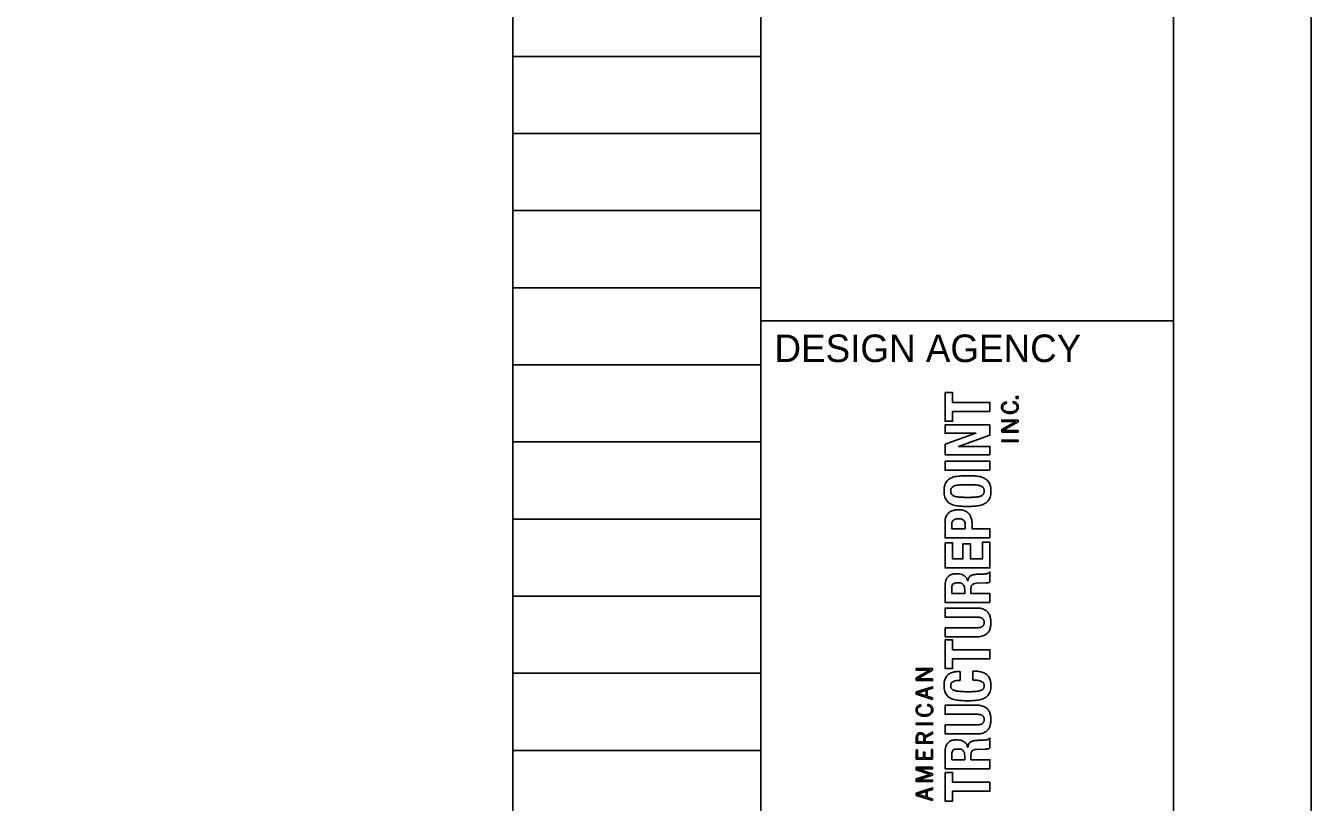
# Model space of a CAD drawing. Extents: x 0 to 84.3, y -13.4 to 22.
# Drawn here: x 29.33 to 34, y 2.751 to 5.571 of the extents above; entities that cross this region are included whole.
import ezdxf

# ---------------------------------------------------------------- set-up
doc = ezdxf.new("R2010")
doc.units = 0
for name, color, linetype in [('SH_Border', 7, 'Continuous'), ('SH_Cut_Line', 7, 'Continuous'), ('SH_Data', 7, 'Continuous')]:
    doc.layers.add(name, color=color, linetype=linetype)

msp = doc.modelspace()

# ---------------------------------------------------------------- linework, layer by layer
at = {"layer": 'SH_Border'}
for p, q in [((32, 0.5), (32, 21.5)), ((32, 4.5), (33.5, 4.5))]:
    msp.add_line(p, q, dxfattribs=at)
msp.add_lwpolyline([(1.5, 21.5), (33.5, 21.5), (33.5, 0.5), (1.5, 0.5)], close=True, dxfattribs=at)
at = {"layer": 'SH_Cut_Line'}
msp.add_lwpolyline([(0, 0), (34, 0), (34, 22), (0, 22)], close=True, dxfattribs=at)
at = {"layer": 'SH_Data'}
for p, q in [((31.1, 0.98), (31.1, 21.14)), ((32, 0.98), (32, 21.14)), ((31.1, 5.46), (32, 5.46)), ((31.1, 5.18), (32, 5.18)), ((31.1, 4.9), (32, 4.9)), ((31.1, 4.62), (32, 4.62)), ((31.1, 4.34), (32, 4.34)), ((31.1, 4.06), (32, 4.06)), ((31.1, 3.78), (32, 3.78)), ((31.1, 3.5), (32, 3.5)), ((32.75, 3.5), (32.75, 3.5)), ((32.75, 3.5), (32.75, 3.5)), ((31.1, 3.22), (32, 3.22)), ((31.1, 2.94), (32, 2.94))]:
    msp.add_line(p, q, dxfattribs=at)
for points in [[(32.6696, 4.2393), (32.6967, 4.2393), (32.6967, 4.2036), (32.8329, 4.2036), (32.8329, 4.1708), (32.6967, 4.1708), (32.6967, 4.1351), (32.6696, 4.1351), (32.6696, 4.2393)], [(32.9349, 4.218), (32.9275, 4.218), (32.9275, 4.225), (32.9349, 4.225), (32.9349, 4.218)], [(32.6696, 4.0513), (32.7815, 4.0912), (32.7815, 4.0916), (32.6696, 4.0916), (32.6696, 4.1218), (32.8329, 4.1218), (32.8329, 4.0842), (32.7185, 4.0439), (32.7185, 4.0435), (32.8329, 4.0435), (32.8329, 4.0134), (32.6696, 4.0134), (32.6696, 4.0513)], [(32.8754, 4.096), (32.8754, 4.1052), (32.925, 4.1335), (32.925, 4.1337), (32.8754, 4.1337), (32.8754, 4.1391), (32.9349, 4.1391), (32.9349, 4.1335), (32.8798, 4.1016), (32.8798, 4.1014), (32.9349, 4.1014), (32.9349, 4.096), (32.8754, 4.096)], [(32.8754, 4.0613), (32.8754, 4.0667), (32.9349, 4.0667), (32.9349, 4.0613), (32.8754, 4.0613)], [(32.8329, 3.957), (32.6696, 3.957), (32.6696, 3.9898), (32.8329, 3.9898), (32.8329, 3.957)], [(32.8329, 3.7115), (32.6696, 3.7115), (32.6696, 3.7691)], [(32.694, 3.7444), (32.7432, 3.7444), (32.7432, 3.759)], [(32.694, 3.7581), (32.694, 3.7444)], [(32.7677, 3.7619), (32.7677, 3.7444), (32.8329, 3.7444), (32.8329, 3.7115)], [(32.6696, 3.6937), (32.6967, 3.6937), (32.6967, 3.6353), (32.7348, 3.6353), (32.7348, 3.6903), (32.7619, 3.6903), (32.7619, 3.6353), (32.8058, 3.6353), (32.8058, 3.696), (32.8329, 3.696), (32.8329, 3.6025), (32.6696, 3.6025), (32.6696, 3.6937)], [(32.7519, 3.5538), (32.7524, 3.5538)], [(32.8316, 3.5875), (32.8329, 3.5875), (32.8329, 3.5518)], [(32.8329, 3.4763), (32.6696, 3.4763), (32.6696, 3.5373)], [(32.694, 3.5249), (32.694, 3.5092)], [(32.694, 3.5092), (32.7409, 3.5092), (32.7409, 3.5231)], [(32.7638, 3.527), (32.7638, 3.5092), (32.8329, 3.5092), (32.8329, 3.4763)], [(32.8158, 3.5477), (32.7844, 3.5468)], [(32.6696, 3.3411), (32.6967, 3.3411), (32.6967, 3.3054), (32.8329, 3.3054), (32.8329, 3.2726), (32.6967, 3.2726), (32.6967, 3.2369), (32.6696, 3.2369), (32.6696, 3.3411)], [(32.565, 3.1938), (32.565, 3.2029), (32.6146, 3.2313), (32.6146, 3.2315), (32.565, 3.2315), (32.565, 3.2369), (32.6245, 3.2369), (32.6245, 3.2313), (32.5694, 3.1994), (32.5694, 3.1992), (32.6245, 3.1992), (32.6245, 3.1938), (32.565, 3.1938)], [(32.6245, 3.1249), (32.565, 3.1439), (32.565, 3.1523), (32.6245, 3.1711), (32.6245, 3.1653), (32.605, 3.1593), (32.605, 3.1368), (32.6245, 3.1307), (32.6245, 3.1249)], [(32.6006, 3.1382), (32.6006, 3.158), (32.5694, 3.1481), (32.5694, 3.148), (32.6006, 3.1382)], [(32.565, 3.0336), (32.565, 3.039), (32.6245, 3.039), (32.6245, 3.0336), (32.565, 3.0336)], [(32.5963, 2.9917), (32.6245, 3.0063), (32.6245, 3.0004), (32.5973, 2.9865), (32.5973, 2.9711), (32.6245, 2.9711), (32.6245, 2.9656), (32.565, 2.9656), (32.565, 2.9858)], [(32.6245, 2.9074), (32.565, 2.9074), (32.565, 2.9414), (32.5694, 2.9414), (32.5694, 2.9129), (32.5913, 2.9129), (32.5913, 2.9334), (32.5958, 2.9334), (32.5958, 2.9129), (32.62, 2.9129), (32.62, 2.943), (32.6245, 2.943), (32.6245, 2.9074)], [(32.5694, 2.9711), (32.5928, 2.9711), (32.5928, 2.9858)], [(32.5694, 2.9858), (32.5694, 2.9711)], [(32.7519, 2.9506), (32.7524, 2.9506)], [(32.8158, 2.9445), (32.7844, 2.9435)], [(32.8316, 2.9843), (32.8329, 2.9843), (32.8329, 2.9486)], [(32.8329, 2.8731), (32.6696, 2.8731), (32.6696, 2.9341)], [(32.694, 2.9217), (32.694, 2.9059)], [(32.694, 2.9059), (32.7409, 2.9059), (32.7409, 2.9198)], [(32.7638, 2.9238), (32.7638, 2.9059), (32.8329, 2.9059), (32.8329, 2.8731)], [(32.6245, 2.8264), (32.565, 2.8264), (32.565, 2.836), (32.6154, 2.8524), (32.6154, 2.8526), (32.565, 2.8691), (32.565, 2.8787), (32.6245, 2.8787), (32.6245, 2.8732), (32.5694, 2.8732), (32.5694, 2.8731), (32.6245, 2.8551), (32.6245, 2.8499), (32.5694, 2.832), (32.5694, 2.8318), (32.6245, 2.8318), (32.6245, 2.8264)], [(32.6696, 2.86), (32.6967, 2.86), (32.6967, 2.8242), (32.8329, 2.8242), (32.8329, 2.7914), (32.6967, 2.7914), (32.6967, 2.7557), (32.6696, 2.7557), (32.6696, 2.86)], [(32.6245, 2.7575), (32.565, 2.7766), (32.565, 2.7849), (32.6245, 2.8037), (32.6245, 2.7979), (32.605, 2.7919), (32.605, 2.7694), (32.6245, 2.7633), (32.6245, 2.7575)], [(32.6006, 2.7708), (32.6006, 2.7906), (32.5694, 2.7808), (32.5694, 2.7806), (32.6006, 2.7708)]]:
    msp.add_lwpolyline(points, dxfattribs=at)
for points in [[(32.8929, 4.2005), (32.8885, 4.1993), (32.8851, 4.1974), (32.8827, 4.195), (32.8803, 4.1926), (32.8791, 4.1896), (32.8791, 4.186), (32.8791, 4.183), (32.8798, 4.1805), (32.8811, 4.1784), (32.8825, 4.1763), (32.8843, 4.1745), (32.8867, 4.1731), (32.889, 4.1717), (32.8918, 4.1707), (32.895, 4.17), (32.8982, 4.1694), (32.9016, 4.169), (32.9052, 4.169), (32.9088, 4.169), (32.9122, 4.1694), (32.9154, 4.17), (32.9186, 4.1707), (32.9214, 4.1717), (32.9237, 4.1732), (32.9261, 4.1746), (32.9279, 4.1764), (32.9293, 4.1786), (32.9306, 4.1809), (32.9313, 4.1835), (32.9313, 4.1866), (32.9313, 4.189), (32.9309, 4.191), (32.9301, 4.1927), (32.9293, 4.1943), (32.9283, 4.1957), (32.9269, 4.1969), (32.9256, 4.1981), (32.9241, 4.199), (32.9223, 4.1997), (32.9206, 4.2005), (32.9187, 4.2011), (32.9168, 4.2016), (32.9168, 4.2016), (32.9177, 4.2067), (32.9177, 4.2067), (32.9203, 4.2062), (32.9228, 4.2054), (32.925, 4.2044), (32.9272, 4.2033), (32.9291, 4.202), (32.9307, 4.2004), (32.9323, 4.1988), (32.9336, 4.1969), (32.9345, 4.1946), (32.9354, 4.1924), (32.9358, 4.1896), (32.9358, 4.1865), (32.9358, 4.1829), (32.9351, 4.1797), (32.9336, 4.1768), (32.9322, 4.174), (32.9301, 4.1716), (32.9274, 4.1697), (32.9247, 4.1677), (32.9215, 4.1662), (32.9177, 4.1652), (32.914, 4.1641), (32.9098, 4.1636), (32.9052, 4.1636), (32.9006, 4.1636), (32.8964, 4.1641), (32.8927, 4.1652), (32.889, 4.1662), (32.8857, 4.1677), (32.883, 4.1697), (32.8803, 4.1716), (32.8783, 4.174), (32.8768, 4.1768), (32.8754, 4.1797), (32.8746, 4.1829), (32.8746, 4.1865), (32.8746, 4.1891), (32.8751, 4.1915), (32.8759, 4.1936), (32.8768, 4.1957), (32.878, 4.1975), (32.8796, 4.1991), (32.8811, 4.2006), (32.8829, 4.202), (32.885, 4.203), (32.8871, 4.204), (32.8894, 4.2049), (32.8918, 4.2056), (32.8918, 4.2056), (32.8929, 4.2005), (32.8929, 4.2005)], [(32.7511, 3.8258), (32.7387, 3.8258), (32.7273, 3.8264), (32.7168, 3.8275), (32.7064, 3.8287), (32.6974, 3.8312), (32.6899, 3.8351), (32.6825, 3.839), (32.6766, 3.8446), (32.6724, 3.8519), (32.6682, 3.8593), (32.6661, 3.8691), (32.6661, 3.8815), (32.6661, 3.8939), (32.6682, 3.9038), (32.6724, 3.9111), (32.6766, 3.9184), (32.6825, 3.9241), (32.6899, 3.928), (32.6974, 3.9319), (32.7064, 3.9344), (32.7168, 3.9355), (32.7273, 3.9367), (32.7387, 3.9373), (32.7511, 3.9373), (32.7578, 3.9373), (32.7643, 3.9371), (32.7705, 3.9367)], [(32.7705, 3.9367), (32.7756, 3.9365), (32.7806, 3.9361), (32.7853, 3.9355), (32.7957, 3.9344), (32.8047, 3.9319), (32.8122, 3.928), (32.8197, 3.9241), (32.8255, 3.9184), (32.8297, 3.9111), (32.8339, 3.9038), (32.836, 3.8939), (32.836, 3.8815), (32.836, 3.8691), (32.8339, 3.8593), (32.8297, 3.8519), (32.8255, 3.8446), (32.8197, 3.839), (32.8122, 3.8351), (32.8047, 3.8312), (32.7957, 3.8287), (32.7853, 3.8275), (32.7748, 3.8264), (32.7634, 3.8258), (32.7511, 3.8258)], [(32.7511, 3.8586), (32.762, 3.8586), (32.7713, 3.8589), (32.779, 3.8594), (32.7867, 3.86), (32.7929, 3.8611), (32.7978, 3.8627), (32.8025, 3.8643), (32.806, 3.8666), (32.8082, 3.8696), (32.8105, 3.8726), (32.8116, 3.8766), (32.8116, 3.8815), (32.8116, 3.8865), (32.8105, 3.8904), (32.8082, 3.8934), (32.806, 3.8964), (32.8025, 3.8988), (32.7978, 3.9004), (32.7929, 3.902), (32.7867, 3.9031), (32.779, 3.9036), (32.7713, 3.9042), (32.762, 3.9044), (32.7511, 3.9044), (32.7401, 3.9044), (32.7308, 3.9042), (32.7232, 3.9036), (32.7156, 3.9031), (32.7094, 3.902), (32.7045, 3.9004), (32.6996, 3.8988), (32.6961, 3.8964), (32.6939, 3.8934), (32.6917, 3.8904), (32.6906, 3.8865), (32.6906, 3.8815), (32.6906, 3.8766), (32.6917, 3.8726), (32.6939, 3.8696), (32.6961, 3.8666), (32.6996, 3.8643), (32.7045, 3.8627), (32.7094, 3.8611), (32.7156, 3.86), (32.7232, 3.8594), (32.7308, 3.8589), (32.7401, 3.8586), (32.7511, 3.8586)], [(32.6696, 3.7691), (32.6696, 3.7774), (32.671, 3.7845), (32.6738, 3.7902), (32.6766, 3.7959), (32.6803, 3.8005), (32.6849, 3.804), (32.6895, 3.8075), (32.6947, 3.81), (32.7005, 3.8115), (32.7064, 3.8131), (32.7124, 3.8138), (32.7185, 3.8138), (32.727, 3.8138), (32.7344, 3.8126), (32.7406, 3.8101), (32.7467, 3.8075), (32.7518, 3.804), (32.7558, 3.7995), (32.7597, 3.795), (32.7627, 3.7896), (32.7647, 3.7832), (32.7667, 3.7768), (32.7677, 3.7697), (32.7677, 3.7619)], [(32.7432, 3.759), (32.7432, 3.7656), (32.7413, 3.7709), (32.7373, 3.7749), (32.7334, 3.779), (32.7273, 3.781), (32.719, 3.781), (32.7109, 3.781), (32.7048, 3.7792), (32.7005, 3.7757), (32.6962, 3.7722), (32.694, 3.7663), (32.694, 3.7581)], [(32.6696, 3.5373), (32.6696, 3.5509), (32.6731, 3.5616), (32.6801, 3.5693), (32.6871, 3.5771), (32.6976, 3.5809), (32.7117, 3.5809), (32.7227, 3.5809), (32.7316, 3.5787), (32.7386, 3.5743), (32.7455, 3.5699), (32.75, 3.5631), (32.7519, 3.5538)], [(32.7524, 3.5538), (32.7532, 3.5594), (32.7546, 3.5639), (32.7566, 3.5673), (32.7587, 3.5707), (32.7617, 3.5733), (32.7655, 3.5752), (32.7694, 3.5771), (32.7744, 3.5784), (32.7803, 3.579), (32.7863, 3.5796), (32.7936, 3.58), (32.8023, 3.5802), (32.811, 3.5803), (32.8176, 3.5808), (32.8222, 3.5816), (32.8268, 3.5825), (32.8299, 3.5844), (32.8316, 3.5875)], [(32.8329, 3.5518), (32.8307, 3.5501), (32.828, 3.5491), (32.825, 3.5486), (32.8221, 3.5482), (32.819, 3.5479), (32.8158, 3.5477)], [(32.7409, 3.5231), (32.7409, 3.5311), (32.7391, 3.5373), (32.7354, 3.5416), (32.7316, 3.5459), (32.7254, 3.5481), (32.7166, 3.5481), (32.7015, 3.5481), (32.694, 3.5404), (32.694, 3.5249)], [(32.7844, 3.5468), (32.778, 3.5465), (32.773, 3.5448), (32.7693, 3.5418), (32.7657, 3.5388), (32.7638, 3.5338), (32.7638, 3.527)], [(32.6696, 3.3852), (32.6696, 3.3852), (32.7832, 3.3852), (32.7832, 3.3852), (32.7874, 3.3852), (32.7911, 3.3854), (32.7946, 3.386), (32.798, 3.3865), (32.8009, 3.3875), (32.8035, 3.389), (32.806, 3.3904), (32.8079, 3.3924), (32.8094, 3.3949), (32.8108, 3.3975), (32.8116, 3.4006), (32.8116, 3.4045), (32.8116, 3.4083), (32.8108, 3.4115), (32.8094, 3.414), (32.8079, 3.4165), (32.806, 3.4185), (32.8035, 3.4199), (32.8009, 3.4214), (32.798, 3.4224), (32.7946, 3.4229), (32.7911, 3.4235), (32.7874, 3.4237), (32.7832, 3.4237), (32.7832, 3.4237), (32.6696, 3.4237), (32.6696, 3.4237), (32.6696, 3.4237), (32.6696, 3.4566), (32.6696, 3.4566), (32.6696, 3.4566), (32.7834, 3.4566), (32.7834, 3.4566), (32.7938, 3.4566), (32.8023, 3.4551), (32.8091, 3.4522), (32.8159, 3.4493), (32.8213, 3.4454), (32.8252, 3.4406), (32.8292, 3.4357), (32.832, 3.4301), (32.8336, 3.4239), (32.8352, 3.4176), (32.836, 3.4112), (32.836, 3.4045), (32.836, 3.3978), (32.8353, 3.3913), (32.8339, 3.385), (32.8326, 3.3788), (32.8299, 3.3732), (32.826, 3.3683), (32.8222, 3.3635), (32.8168, 3.3596), (32.81, 3.3567), (32.8033, 3.3538), (32.7944, 3.3524), (32.7834, 3.3524), (32.7834, 3.3524), (32.6696, 3.3524), (32.6696, 3.3524), (32.6696, 3.3524), (32.6696, 3.3852), (32.6696, 3.3852)], [(32.7247, 3.1935), (32.7128, 3.1935), (32.7041, 3.1921), (32.6987, 3.1892), (32.6933, 3.1864), (32.6906, 3.1812), (32.6906, 3.1737), (32.6906, 3.1696), (32.6917, 3.1662), (32.6939, 3.1635), (32.6961, 3.1608), (32.6997, 3.1587), (32.7046, 3.1572), (32.7095, 3.1556), (32.716, 3.1546), (32.724, 3.154), (32.732, 3.1533), (32.7418, 3.153), (32.7533, 3.153), (32.7657, 3.153), (32.7756, 3.1535), (32.7832, 3.1543), (32.7909, 3.1551), (32.7968, 3.1565), (32.8009, 3.1582), (32.8051, 3.16), (32.8079, 3.1622), (32.8094, 3.1649), (32.8108, 3.1676), (32.8116, 3.1707), (32.8116, 3.1743), (32.8116, 3.1772), (32.8111, 3.1799), (32.8101, 3.1824), (32.8091, 3.185), (32.8071, 3.1872), (32.8041, 3.189), (32.8011, 3.1909), (32.7969, 3.1923), (32.7915, 3.1934), (32.7861, 3.1945), (32.779, 3.195), (32.7701, 3.195), (32.7701, 3.195), (32.7701, 3.2279), (32.7701, 3.2279), (32.779, 3.2279), (32.7874, 3.2272), (32.7953, 3.2258), (32.8032, 3.2244), (32.8102, 3.2219), (32.8163, 3.2181), (32.8224, 3.2144), (32.8272, 3.2091), (32.8307, 3.2023), (32.8342, 3.1955), (32.836, 3.1867), (32.836, 3.1759), (32.836, 3.1635), (32.8339, 3.1536), (32.8297, 3.1463), (32.8255, 3.139), (32.8197, 3.1334), (32.8122, 3.1295), (32.8047, 3.1256), (32.7957, 3.1231), (32.7853, 3.1219), (32.7748, 3.1208), (32.7634, 3.1202), (32.7511, 3.1202), (32.7387, 3.1202), (32.7273, 3.1208), (32.7168, 3.1219), (32.7064, 3.1231), (32.6974, 3.1256), (32.6899, 3.1295), (32.6825, 3.1334), (32.6766, 3.139), (32.6724, 3.1463), (32.6682, 3.1536), (32.6661, 3.1634), (32.6661, 3.1758), (32.6661, 3.1875), (32.6681, 3.1968), (32.6719, 3.2036), (32.6757, 3.2104), (32.6806, 3.2154), (32.6865, 3.2188), (32.6924, 3.2221), (32.6988, 3.2242), (32.7056, 3.2251), (32.7124, 3.2259), (32.7187, 3.2263), (32.7247, 3.2263), (32.7247, 3.2263), (32.7247, 3.1935), (32.7247, 3.1935)], [(32.5824, 3.1009), (32.5781, 3.0997), (32.5747, 3.0978), (32.5723, 3.0954), (32.5699, 3.0931), (32.5687, 3.09), (32.5687, 3.0864), (32.5687, 3.0835), (32.5694, 3.0809), (32.5707, 3.0788), (32.572, 3.0767), (32.5739, 3.0749), (32.5763, 3.0735), (32.5786, 3.0721), (32.5814, 3.0711), (32.5846, 3.0704), (32.5878, 3.0698), (32.5912, 3.0694), (32.5948, 3.0694), (32.5984, 3.0694), (32.6018, 3.0698), (32.605, 3.0704), (32.6082, 3.0711), (32.6109, 3.0721), (32.6133, 3.0736), (32.6157, 3.075), (32.6175, 3.0768), (32.6189, 3.079), (32.6202, 3.0813), (32.6209, 3.0839), (32.6209, 3.087), (32.6209, 3.0894), (32.6205, 3.0914), (32.6197, 3.0931), (32.6189, 3.0947), (32.6178, 3.0961), (32.6165, 3.0973), (32.6152, 3.0985), (32.6137, 3.0994), (32.6119, 3.1001), (32.6101, 3.1009), (32.6083, 3.1015), (32.6064, 3.102), (32.6064, 3.102), (32.6073, 3.1071), (32.6073, 3.1071), (32.6099, 3.1066), (32.6124, 3.1058), (32.6146, 3.1048), (32.6168, 3.1037), (32.6187, 3.1024), (32.6203, 3.1008), (32.6219, 3.0992), (32.6232, 3.0973), (32.624, 3.095), (32.6249, 3.0927), (32.6254, 3.09), (32.6254, 3.0869), (32.6254, 3.0833), (32.6246, 3.0801), (32.6232, 3.0772), (32.6217, 3.0744), (32.6197, 3.072), (32.617, 3.0701), (32.6143, 3.0681), (32.611, 3.0666), (32.6073, 3.0656), (32.6036, 3.0645), (32.5994, 3.064), (32.5948, 3.064), (32.5902, 3.064), (32.586, 3.0645), (32.5823, 3.0656), (32.5785, 3.0666), (32.5753, 3.0681), (32.5726, 3.0701), (32.5699, 3.072), (32.5678, 3.0744), (32.5664, 3.0772), (32.5649, 3.0801), (32.5642, 3.0833), (32.5642, 3.0869), (32.5642, 3.0895), (32.5646, 3.0919), (32.5655, 3.094), (32.5664, 3.0961), (32.5676, 3.0979), (32.5691, 3.0995), (32.5707, 3.1011), (32.5725, 3.1024), (32.5746, 3.1034), (32.5767, 3.1044), (32.579, 3.1053), (32.5814, 3.106), (32.5814, 3.106), (32.5824, 3.1009), (32.5824, 3.1009)], [(32.6696, 3.0325), (32.6696, 3.0325), (32.7832, 3.0325), (32.7832, 3.0325), (32.7874, 3.0325), (32.7911, 3.0328), (32.7946, 3.0333), (32.798, 3.0338), (32.8009, 3.0348), (32.8035, 3.0363), (32.806, 3.0377), (32.8079, 3.0397), (32.8094, 3.0422), (32.8108, 3.0448), (32.8116, 3.0479), (32.8116, 3.0518), (32.8116, 3.0556), (32.8108, 3.0588), (32.8094, 3.0613), (32.8079, 3.0638), (32.806, 3.0658), (32.8035, 3.0673), (32.8009, 3.0687), (32.798, 3.0697), (32.7946, 3.0702), (32.7911, 3.0708), (32.7874, 3.071), (32.7832, 3.071), (32.7832, 3.071), (32.6696, 3.071), (32.6696, 3.071), (32.6696, 3.071), (32.6696, 3.1039), (32.6696, 3.1039), (32.6696, 3.1039), (32.7834, 3.1039), (32.7834, 3.1039), (32.7938, 3.1039), (32.8023, 3.1024), (32.8091, 3.0995), (32.8159, 3.0966), (32.8213, 3.0928), (32.8252, 3.0879), (32.8292, 3.083), (32.832, 3.0774), (32.8336, 3.0712), (32.8352, 3.0649), (32.836, 3.0585), (32.836, 3.0518), (32.836, 3.0451), (32.8353, 3.0386), (32.8339, 3.0323), (32.8326, 3.0261), (32.8299, 3.0205), (32.826, 3.0157), (32.8222, 3.0108), (32.8168, 3.0069), (32.81, 3.004), (32.8033, 3.0011), (32.7944, 2.9997), (32.7834, 2.9997), (32.7834, 2.9997), (32.6696, 2.9997), (32.6696, 2.9997), (32.6696, 2.9997), (32.6696, 3.0325), (32.6696, 3.0325)], [(32.565, 2.9858), (32.565, 2.9917), (32.5664, 2.9962), (32.5694, 2.9994), (32.5723, 3.0025), (32.5762, 3.0041), (32.5811, 3.0041), (32.5851, 3.0041), (32.5883, 3.0031), (32.5909, 3.0011), (32.5934, 2.9991), (32.5952, 2.996), (32.5963, 2.9917)], [(32.5928, 2.9858), (32.5928, 2.9897), (32.5918, 2.9929), (32.5897, 2.9952), (32.5877, 2.9975), (32.5848, 2.9987), (32.5811, 2.9987), (32.5775, 2.9987), (32.5746, 2.9976), (32.5725, 2.9954), (32.5705, 2.9933), (32.5694, 2.9901), (32.5694, 2.9858)], [(32.6696, 2.9341), (32.6696, 2.9477), (32.6731, 2.9584), (32.6801, 2.9661), (32.6871, 2.9738), (32.6976, 2.9777), (32.7117, 2.9777), (32.7227, 2.9777), (32.7316, 2.9755), (32.7386, 2.9711), (32.7455, 2.9667), (32.75, 2.9598), (32.7519, 2.9506)], [(32.7409, 2.9198), (32.7409, 2.9279), (32.7391, 2.934), (32.7354, 2.9384), (32.7316, 2.9427), (32.7254, 2.9449), (32.7166, 2.9449), (32.7015, 2.9449), (32.694, 2.9371), (32.694, 2.9217)], [(32.7524, 2.9506), (32.7532, 2.9562), (32.7546, 2.9607), (32.7566, 2.9641), (32.7587, 2.9674), (32.7617, 2.9701), (32.7655, 2.972), (32.7694, 2.9739), (32.7744, 2.9752), (32.7803, 2.9758), (32.7863, 2.9764), (32.7936, 2.9768), (32.8023, 2.9769), (32.811, 2.9771), (32.8176, 2.9776), (32.8222, 2.9784), (32.8268, 2.9793), (32.8299, 2.9812), (32.8316, 2.9843)], [(32.7844, 2.9435), (32.778, 2.9432), (32.773, 2.9416), (32.7693, 2.9386), (32.7657, 2.9355), (32.7638, 2.9306), (32.7638, 2.9238)], [(32.8329, 2.9486), (32.8307, 2.9469), (32.828, 2.9458), (32.825, 2.9454), (32.8221, 2.9449), (32.819, 2.9446), (32.8158, 2.9445)]]:
    msp.add_open_spline(points, degree=3, dxfattribs=at)

# ---------------------------------------------------------------- texts
msp.add_text('DESIGN AGENCY', height=0.1, dxfattribs=at).set_placement((32.05, 4.35))

doc.saveas('drawing.dxf')
